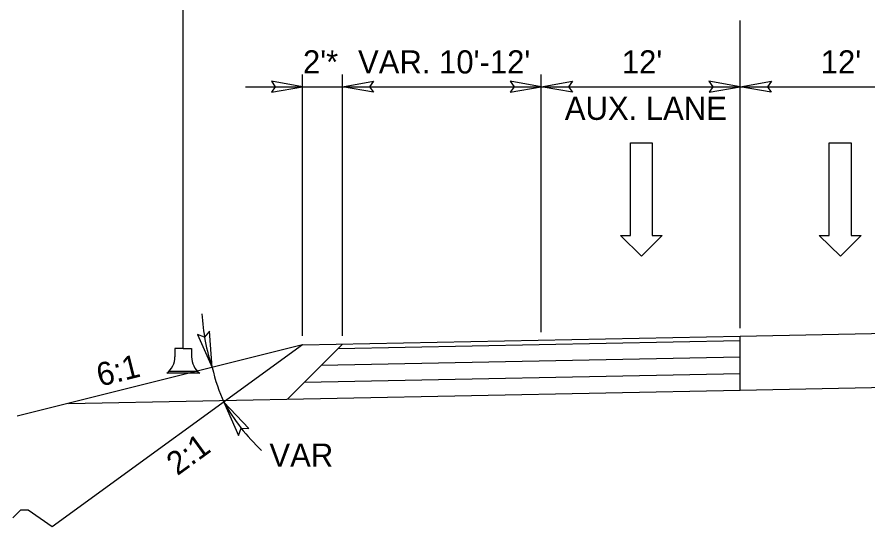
# Model space of a CAD drawing. Extents: x 1726790 to 1728895, y 539219 to 541550.
# Drawn here: x 1727008.5 to 1727265.4, y 541267.5 to 541421.5 of the extents above; entities that cross this region are included whole.
import ezdxf

# ---------------------------------------------------------------- set-up
doc = ezdxf.new("R2010")
doc.units = 0
for name, color, linetype in [('Default', 7, 'Continuous'), ('Prop Dimension Text', 7, 'Continuous'), ('Typical Hinge Slope Interstate CELL', 7, 'Continuous'), ('Typical Pavement Slope CELL', 7, 'Continuous'), ('Typical Pavement Slope Information CELL', 7, 'Continuous')]:
    doc.layers.add(name, color=color, linetype=linetype)

msp = doc.modelspace()

# ---------------------------------------------------------------- linework, layer by layer
at = {"layer": 'Default'}
for p, q in [((1727058.65, 541321.41), (1727058.65, 541482.6)), ((1727226.79, 541327.57), (1727226.79, 541420.48)), ((1727094.68, 541325.17), (1727094.68, 541404.16)), ((1727106.69, 541325.17), (1727106.69, 541404.16)), ((1727166.74, 541326.37), (1727166.74, 541404.16)), ((1727226.79, 541327.57), (1727226.79, 541404.16)), ((1727106.69, 541325.17), (1727106.69, 541402.96)), ((1727077.42, 541400.46), (1727106.8, 541400.46)), ((1727106.8, 541400.46), (1727166.85, 541400.46)), ((1727166.85, 541400.46), (1727226.89, 541400.46)), ((1727226.89, 541400.46), (1727286.94, 541400.46)), ((1727193.63, 541355.56), (1727193.63, 541383.56)), ((1727193.63, 541383.56), (1727200.23, 541383.56)), ((1727200.23, 541383.56), (1727200.23, 541355.56)), ((1727253.68, 541355.56), (1727253.68, 541383.56)), ((1727253.68, 541383.56), (1727260.28, 541383.56)), ((1727260.28, 541383.56), (1727260.28, 541355.56)), ((1727197.03, 541349.26), (1727190.63, 541355.56)), ((1727190.63, 541355.56), (1727193.63, 541355.56)), ((1727203.23, 541355.56), (1727197.03, 541349.26)), ((1727200.23, 541355.56), (1727203.23, 541355.56)), ((1727257.08, 541349.26), (1727250.68, 541355.56)), ((1727250.68, 541355.56), (1727253.68, 541355.56)), ((1727263.28, 541355.56), (1727257.08, 541349.26)), ((1727260.28, 541355.56), (1727263.28, 541355.56)), ((1727058.65, 541321.41), (1727056.15, 541321.41)), ((1727056.15, 541321.41), (1727056.15, 541318.91)), ((1727058.65, 541321.41), (1727061.15, 541321.41)), ((1727061.15, 541321.41), (1727061.15, 541318.91)), ((1727063.65, 541313.91), (1727053.65, 541313.91)), ((1727063.07, 541314.41), (1727054.24, 541314.41))]:
    msp.add_line(p, q, dxfattribs=at)
for points in [[(1727085.3, 541398.85), (1727094.68, 541400.46), (1727085.25, 541402.13), (1727086.45, 541400.46)], [(1727116.07, 541398.85), (1727106.69, 541400.46), (1727116.12, 541402.13), (1727114.92, 541400.46)], [(1727157.36, 541398.85), (1727166.74, 541400.46), (1727157.31, 541402.13), (1727158.51, 541400.46)], [(1727176.12, 541398.85), (1727166.74, 541400.46), (1727176.17, 541402.13), (1727174.97, 541400.46)], [(1727217.41, 541398.85), (1727226.79, 541400.46), (1727217.36, 541402.13), (1727218.55, 541400.46)], [(1727236.16, 541398.85), (1727226.79, 541400.46), (1727236.22, 541402.13), (1727235.02, 541400.46)], [(1727062.93, 541325.66), (1727067.38, 541315.63), (1727066.58, 541326.64), (1727065.05, 541324.83)], [(1727078.46, 541297.21), (1727070.93, 541305.19), (1727075.35, 541295.07), (1727076.18, 541297.28)], [(1727078.46, 541297.21), (1727070.93, 541305.19), (1727075.35, 541295.07), (1727076.18, 541297.28)]]:
    msp.add_lwpolyline(points, close=True, dxfattribs=at)
for centre, start, end in [((1727049.9, 541318.91), 306.8699, 0), ((1727067.4, 541318.91), 180, 233.1301)]:
    msp.add_arc(centre, 6.25, start, end, dxfattribs=at)
at = {"layer": 'Typical Hinge Slope Interstate CELL'}
msp.add_lwpolyline([(1727019.07, 541267.47), (1727011.86, 541272.53), (1727009.52, 541272.53), (1727007.18, 541270.21)], dxfattribs=at)
for centre, start, end in [((1727124.55, 541334.97), 182.9343, 198.686), ((1727123.68, 541334.52), 209.0778, 226.6941), ((1727123.68, 541334.52), 209.0778, 226.6941)]:
    msp.add_arc(centre, 60.35, start, end, dxfattribs=at)
msp.add_ellipse((1727096.27, 541350.06), major_axis=(-9.27, -59.64), ratio=0.5, start_param=5.403228, end_param=5.638322, dxfattribs=at)
at = {"layer": 'Typical Pavement Slope CELL'}
for p, q in [((1727226.79, 541325.1), (1727461.04, 541329.79)), ((1727094.68, 541322.46), (1727226.76, 541325.1)), ((1727105.41, 541321.42), (1727226.79, 541323.85)), ((1727226.79, 541308.85), (1727226.79, 541325.1)), ((1727094.68, 541322.46), (1727008.46, 541300.91)), ((1727094.68, 541322.46), (1727019.07, 541267.47)), ((1727106.69, 541322.7), (1727090.1, 541306.11)), ((1727100.31, 541316.32), (1727226.79, 541318.85)), ((1727095.21, 541311.22), (1727226.79, 541313.85)), ((1727226.79, 541308.85), (1727461.04, 541313.53)), ((1727024, 541304.79), (1727226.79, 541308.85))]:
    msp.add_line(p, q, dxfattribs=at)

# ---------------------------------------------------------------- texts
at = {"layer": 'Prop Dimension Text'}
for s, rotation, p in [('6:1', 14.0362, (1727033.49, 541309.84)), ('2:1', 36.0298, (1727056.88, 541282.8))]:
    msp.add_text(s, height=7.005, rotation=rotation, dxfattribs=at).set_placement(p)
msp.add_text('VAR', height=7.005, dxfattribs=at).set_placement((1727084.67, 541285.66))
at = {"layer": 'Typical Pavement Slope Information CELL'}
for s, height, p in [("2'*", 7.005, (1727094.79, 541404.47)), ("VAR. 10'-12'", 7.0055, (1727111.42, 541404.47)), ("12'", 7.005, (1727191.06, 541404.47)), ("12'", 7.005, (1727251.11, 541404.47)), ('AUX. LANE', 7.005, (1727173.85, 541390.46))]:
    msp.add_text(s, height=height, dxfattribs=at).set_placement(p)

doc.saveas('drawing.dxf')
